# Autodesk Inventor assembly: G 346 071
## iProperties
Company: Mayer & Müller AG Schaltgeräte
Created: 2006-09
Part Number: G 346 071
Description: Isolator, kompl.
Document SubType Name: Assembly
Designer: I.Baliuc
Mass: 29.8914 g
Surface Area: 201.754 cm^2
Volume: 31.7994 cm^3
Density: 0.94 g/cm^3
Author: T.Messerschmitt
Revision Number: 346071
